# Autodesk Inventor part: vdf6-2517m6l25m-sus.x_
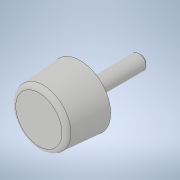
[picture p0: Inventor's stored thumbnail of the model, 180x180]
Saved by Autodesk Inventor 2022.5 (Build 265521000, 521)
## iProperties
Created: 2021-08
Part Number: vdf6-2517m6l25m-sus.x_
Material: 一般
Document SubType Name: Modeling
Designer: ImaoCorp
Density: 1 g/cm^3
Appearance: 既定
Sending System: SOLIDWORKS 2019-2019304
MC: AMD64
MC_MODEL: Intel64 Family 6 Model 60 Stepping 3, GenuineIntel
OS: Windows_NT
FRU: Parasolid Version 31.0, build 290,  9- 1-2019
FORMAT: text
GUISE: transmit
KEY: vdf6-2517m6l25m-sus
FILE: vdf6-2517m6l25m-sus.x_t
DATE: Wed Aug 11 14:59:04 2021
Author: ImaoCorp
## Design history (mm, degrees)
feature "Base1"
node "ソリッド1"
